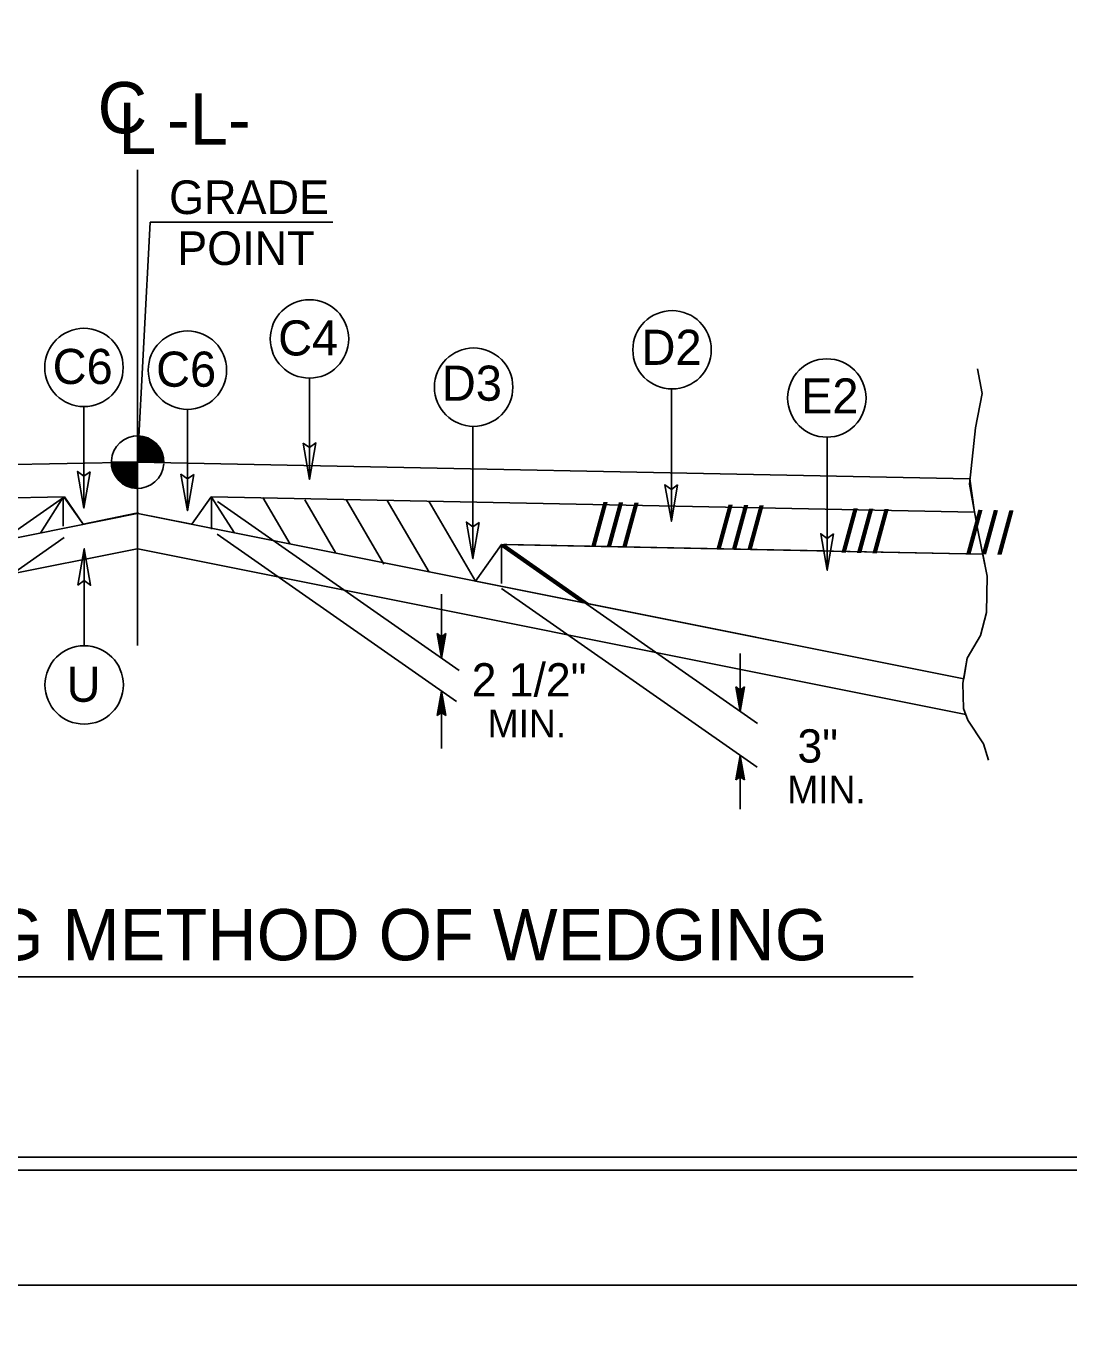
# Model space of a CAD drawing. Extents: x 1901718 to 1902220, y 193828 to 194187.
# Drawn here: x 1902003.79 to 1902024.12, y 194046.89 to 194072.58 of the extents above; entities that cross this region are included whole.
import ezdxf

# ---------------------------------------------------------------- set-up
doc = ezdxf.new("R2010")
doc.units = 0
for name, color, linetype in [('Old_Level_1', 7, 'Continuous'), ('Old_Level_11', 7, 'Continuous'), ('Old_Level_2', 7, 'Continuous'), ('Old_Level_20', 7, 'Continuous'), ('Old_Level_21', 7, 'Continuous'), ('Old_Level_3', 7, 'Continuous'), ('Sheet Border Standard 30in CELL', 7, 'Continuous'), ('Sheet Cutting Line CELL', 7, 'Continuous'), ('Sheet Plot Border Inside CELL', 7, 'Continuous'), ('Sheet Plot Border Outside CELL', 7, 'Continuous')]:
    doc.layers.add(name, color=color, linetype=linetype)

msp = doc.modelspace()

# ---------------------------------------------------------------- linework, layer by layer
at = {"layer": 'Old_Level_1'}
for p, q in [((1902005.956, 194064.077), (1902005.956, 194064.588)), ((1902005.445, 194064.077), (1902005.956, 194064.077)), ((1902005.953, 194063.566), (1902005.953, 194064.071)), ((1902005.956, 194064.077), (1902005.956, 194063.566)), ((1902006.468, 194064.077), (1902005.956, 194064.077)), ((1902005.956, 194063.566), (1902005.956, 194064.077)), ((1902004.51, 194063.386), (1901999.935, 194060.183)), ((1902008.4, 194063.386), (1902008.93, 194062.478)), ((1902007.513, 194063.312), (1902012.226, 194060.011)), ((1902009.215, 194063.344), (1902009.823, 194062.303)), ((1902010.023, 194063.346), (1902010.757, 194062.089)), ((1902010.825, 194063.33), (1902011.642, 194061.928)), ((1902011.636, 194063.313), (1902012.545, 194061.755)), ((1902004.521, 194062.604), (1902000.044, 194059.469)), ((1902007.507, 194062.67), (1902012.174, 194059.403)), ((1902005.947, 194062.385), (1901989.833, 194059.162)), ((1902005.959, 194062.385), (1902022.11, 194059.154)), ((1902012.546, 194061.755), (1902013.055, 194062.471)), ((1902013.055, 194062.471), (1902022.44, 194062.283)), ((1902013.055, 194062.471), (1902013.055, 194061.71)), ((1902013.056, 194062.471), (1902018.046, 194058.976)), ((1902012.545, 194061.755), (1902014.69, 194061.326)), ((1902013.055, 194061.611), (1902018.037, 194058.121)), ((1902011.882, 194061.501), (1902011.882, 194060.253)), ((1902011.882, 194060.253), (1902011.798, 194060.731)), ((1902011.882, 194060.668), (1902011.798, 194060.731)), ((1902011.882, 194060.253), (1902011.809, 194060.722)), ((1902011.821, 194060.713), (1902011.882, 194060.253)), ((1902011.882, 194060.253), (1902011.834, 194060.704)), ((1902011.846, 194060.695), (1902011.882, 194060.253)), ((1902011.882, 194060.253), (1902011.857, 194060.686)), ((1902011.869, 194060.678), (1902011.882, 194060.253)), ((1902011.882, 194060.253), (1902011.966, 194060.731)), ((1902011.966, 194060.731), (1902011.882, 194060.668)), ((1902011.954, 194060.722), (1902011.882, 194060.253)), ((1902011.882, 194060.253), (1902011.942, 194060.713)), ((1902011.93, 194060.704), (1902011.882, 194060.253)), ((1902011.882, 194060.253), (1902011.918, 194060.695)), ((1902011.906, 194060.686), (1902011.882, 194060.253)), ((1902011.882, 194060.253), (1902011.894, 194060.678)), ((1902011.882, 194060.668), (1902011.882, 194060.253)), ((1902017.708, 194060.342), (1902017.708, 194059.213)), ((1902011.882, 194059.607), (1902011.798, 194059.13)), ((1902011.809, 194059.139), (1902011.882, 194059.607)), ((1902011.882, 194059.607), (1902011.821, 194059.148)), ((1902011.834, 194059.157), (1902011.882, 194059.607)), ((1902011.882, 194059.607), (1902011.846, 194059.166)), ((1902011.857, 194059.174), (1902011.882, 194059.607)), ((1902011.882, 194059.607), (1902011.869, 194059.183)), ((1902011.882, 194059.607), (1902011.882, 194058.491)), ((1902011.882, 194059.607), (1902011.966, 194059.13)), ((1902011.882, 194059.192), (1902011.882, 194059.607)), ((1902011.894, 194059.183), (1902011.882, 194059.607)), ((1902011.882, 194059.607), (1902011.906, 194059.174)), ((1902011.918, 194059.166), (1902011.882, 194059.607)), ((1902011.882, 194059.607), (1902011.93, 194059.157)), ((1902011.942, 194059.148), (1902011.882, 194059.607)), ((1902011.882, 194059.607), (1902011.954, 194059.139)), ((1902017.708, 194059.213), (1902017.624, 194059.69)), ((1902017.708, 194059.629), (1902017.624, 194059.69)), ((1902017.708, 194059.213), (1902017.636, 194059.681)), ((1902017.648, 194059.673), (1902017.708, 194059.213)), ((1902017.708, 194059.213), (1902017.659, 194059.665)), ((1902017.671, 194059.655), (1902017.708, 194059.213)), ((1902017.708, 194059.213), (1902017.684, 194059.647)), ((1902017.695, 194059.637), (1902017.708, 194059.213)), ((1902017.708, 194059.213), (1902017.792, 194059.69)), ((1902017.792, 194059.69), (1902017.708, 194059.629)), ((1902017.78, 194059.681), (1902017.708, 194059.213)), ((1902017.708, 194059.213), (1902017.768, 194059.673)), ((1902017.756, 194059.665), (1902017.708, 194059.213)), ((1902017.708, 194059.213), (1902017.743, 194059.655)), ((1902017.732, 194059.647), (1902017.708, 194059.213)), ((1902017.708, 194059.213), (1902017.72, 194059.637)), ((1902017.708, 194059.629), (1902017.708, 194059.213)), ((1902011.798, 194059.13), (1902011.882, 194059.192)), ((1902011.882, 194059.192), (1902011.966, 194059.13)), ((1902017.708, 194058.352), (1902017.624, 194057.875)), ((1902017.636, 194057.884), (1902017.708, 194058.352)), ((1902017.708, 194058.352), (1902017.648, 194057.893)), ((1902017.659, 194057.902), (1902017.708, 194058.352)), ((1902017.708, 194058.352), (1902017.671, 194057.911)), ((1902017.684, 194057.92), (1902017.708, 194058.352)), ((1902017.708, 194058.352), (1902017.695, 194057.928)), ((1902017.708, 194058.352), (1902017.708, 194057.305)), ((1902017.708, 194058.352), (1902017.792, 194057.875)), ((1902017.708, 194057.938), (1902017.708, 194058.352)), ((1902017.72, 194057.928), (1902017.708, 194058.352)), ((1902017.708, 194058.352), (1902017.732, 194057.92)), ((1902017.743, 194057.911), (1902017.708, 194058.352)), ((1902017.708, 194058.352), (1902017.756, 194057.902)), ((1902017.768, 194057.893), (1902017.708, 194058.352)), ((1902017.708, 194058.352), (1902017.78, 194057.884)), ((1902017.624, 194057.875), (1902017.708, 194057.938)), ((1902017.708, 194057.938), (1902017.792, 194057.875))]:
    msp.add_line(p, q, dxfattribs=at)
for points in [[(1902022.34, 194065.896), (1902022.426, 194065.42), (1902022.297, 194064.744), (1902022.181, 194063.649), (1902022.34, 194062.785), (1902022.527, 194061.849), (1902022.513, 194061.143), (1902022.397, 194060.697), (1902022.138, 194060.25), (1902022.052, 194059.761), (1902022.066, 194059.271), (1902022.152, 194059.04), (1902022.454, 194058.579), (1902022.555, 194058.262)], [(1902005.961, 194064.588), (1902005.961, 194064.588), (1902005.961, 194064.077)], [(1902005.971, 194064.588), (1902005.971, 194064.077)], [(1902005.982, 194064.588), (1902005.982, 194064.077)], [(1902005.992, 194064.587), (1902005.992, 194064.077)], [(1902006.003, 194064.587), (1902006.003, 194064.077)], [(1902006.012, 194064.585), (1902006.012, 194064.077)], [(1902006.023, 194064.585), (1902006.023, 194064.077)], [(1902006.032, 194064.583), (1902006.032, 194064.077)], [(1902006.043, 194064.581), (1902006.043, 194064.077)], [(1902006.053, 194064.579), (1902006.053, 194064.077)], [(1902006.064, 194064.578), (1902006.064, 194064.077)], [(1902006.074, 194064.575), (1902006.074, 194064.077)], [(1902006.084, 194064.572), (1902006.084, 194064.077)], [(1902006.094, 194064.569), (1902006.094, 194064.077)], [(1902006.104, 194064.566), (1902006.104, 194064.077)], [(1902006.114, 194064.563), (1902006.114, 194064.077)], [(1902006.125, 194064.56), (1902006.125, 194064.077)], [(1902006.135, 194064.556), (1902006.135, 194064.077)], [(1902006.146, 194064.552), (1902006.146, 194064.077)], [(1902006.156, 194064.548), (1902006.155, 194064.077)], [(1902006.166, 194064.543), (1902006.166, 194064.077)], [(1902006.176, 194064.539), (1902006.176, 194064.077)], [(1902006.186, 194064.534), (1902006.186, 194064.077)], [(1902006.197, 194064.528), (1902006.197, 194064.077)], [(1902006.207, 194064.522), (1902006.207, 194064.077)], [(1902006.217, 194064.516), (1902006.217, 194064.077)], [(1902006.228, 194064.51), (1902006.227, 194064.077)], [(1902006.238, 194064.505), (1902006.238, 194064.077)], [(1902006.247, 194064.497), (1902006.247, 194064.077)], [(1902006.257, 194064.49), (1902006.257, 194064.077)], [(1902006.268, 194064.482), (1902006.268, 194064.077)], [(1902006.278, 194064.474), (1902006.278, 194064.077)], [(1902006.289, 194064.466), (1902006.289, 194064.077)], [(1902006.299, 194064.457), (1902006.299, 194064.077)], [(1902006.31, 194064.447), (1902006.31, 194064.077)], [(1902006.319, 194064.438), (1902006.319, 194064.077)], [(1902006.329, 194064.427), (1902006.329, 194064.077)], [(1902006.34, 194064.415), (1902006.34, 194064.077)], [(1902006.35, 194064.403), (1902006.35, 194064.077)], [(1902006.361, 194064.39), (1902006.361, 194064.077)], [(1902006.371, 194064.377), (1902006.37, 194064.077)], [(1902006.381, 194064.363), (1902006.381, 194064.077)], [(1902006.39, 194064.346), (1902006.39, 194064.077)], [(1902006.401, 194064.329), (1902006.401, 194064.077)], [(1902006.411, 194064.311), (1902006.411, 194064.077)], [(1902006.422, 194064.289), (1902006.422, 194064.077)], [(1902006.432, 194064.265), (1902006.432, 194064.077)], [(1902006.442, 194064.236), (1902006.442, 194064.077)], [(1902006.453, 194064.202), (1902006.453, 194064.077)], [(1902006.462, 194064.149), (1902006.462, 194064.077)], [(1902005.447, 194064.077), (1902005.447, 194064.021)], [(1902005.458, 194064.077), (1902005.458, 194063.961)], [(1902005.469, 194064.077), (1902005.469, 194063.924)], [(1902005.479, 194064.077), (1902005.479, 194063.895)], [(1902005.488, 194064.077), (1902005.488, 194063.869)], [(1902005.498, 194064.077), (1902005.498, 194063.848)], [(1902005.508, 194064.077), (1902005.508, 194063.829)], [(1902005.519, 194064.077), (1902005.519, 194063.811)], [(1902005.529, 194064.077), (1902005.529, 194063.795)], [(1902005.54, 194064.077), (1902005.54, 194063.779)], [(1902005.55, 194064.077), (1902005.55, 194063.766)], [(1902005.56, 194064.077), (1902005.56, 194063.753)], [(1902005.57, 194064.077), (1902005.57, 194063.741)], [(1902005.58, 194064.077), (1902005.58, 194063.729)], [(1902005.591, 194064.077), (1902005.591, 194063.719)], [(1902005.601, 194064.077), (1902005.601, 194063.71)], [(1902005.612, 194064.077), (1902005.612, 194063.699)], [(1902005.622, 194064.077), (1902005.621, 194063.69)], [(1902005.631, 194064.077), (1902005.631, 194063.681)], [(1902005.642, 194064.077), (1902005.642, 194063.674)], [(1902005.652, 194064.077), (1902005.652, 194063.666)], [(1902005.663, 194064.077), (1902005.663, 194063.659)], [(1902005.673, 194064.077), (1902005.673, 194063.651)], [(1902005.683, 194064.077), (1902005.683, 194063.644)], [(1902005.693, 194064.077), (1902005.693, 194063.638)], [(1902005.703, 194064.077), (1902005.703, 194063.632)], [(1902005.713, 194064.077), (1902005.713, 194063.627)], [(1902005.723, 194064.077), (1902005.723, 194063.621)], [(1902005.734, 194064.077), (1902005.734, 194063.616)], [(1902005.744, 194064.077), (1902005.744, 194063.611)], [(1902005.755, 194064.077), (1902005.755, 194063.606)], [(1902005.765, 194064.077), (1902005.765, 194063.603)], [(1902005.775, 194064.077), (1902005.775, 194063.599)], [(1902005.786, 194064.077), (1902005.786, 194063.594)], [(1902005.795, 194064.077), (1902005.795, 194063.591)], [(1902005.806, 194064.077), (1902005.806, 194063.588)], [(1902005.816, 194064.077), (1902005.816, 194063.585)], [(1902005.826, 194064.077), (1902005.826, 194063.583)], [(1902005.837, 194064.077), (1902005.836, 194063.579)], [(1902005.846, 194064.077), (1902005.846, 194063.578)], [(1902005.857, 194064.077), (1902005.857, 194063.575)], [(1902005.866, 194064.077), (1902005.866, 194063.573)], [(1902005.877, 194064.077), (1902005.877, 194063.572)], [(1902005.887, 194064.077), (1902005.887, 194063.57)], [(1902005.898, 194064.077), (1902005.898, 194063.569)], [(1902005.908, 194064.077), (1902005.908, 194063.567)], [(1902005.918, 194064.077), (1902005.918, 194063.567)], [(1902005.929, 194064.077), (1902005.928, 194063.566)], [(1902005.938, 194064.077), (1902005.938, 194063.566)], [(1902005.949, 194064.077), (1902005.949, 194063.566), (1902005.949, 194063.566)]]:
    msp.add_lwpolyline(points, dxfattribs=at)
for start, end in [(358.0003, 356.1713), (359.9905, 89.9905), (179.9905, 268.7186), (269.6533, 269.9905)]:
    msp.add_arc((1902005.956, 194064.077), 0.512, start, end, dxfattribs=at)
at = {"layer": 'Old_Level_11'}
for p, q in [((1902005.952, 194060.497), (1902005.952, 194069.78)), ((1902009.308, 194065.717), (1902009.308, 194063.739)), ((1902016.366, 194065.504), (1902016.366, 194062.923)), ((1902004.91, 194065.16), (1902004.91, 194063.182)), ((1902006.927, 194065.107), (1902006.927, 194063.129)), ((1902012.495, 194064.775), (1902012.495, 194062.194)), ((1902019.407, 194064.563), (1902019.407, 194061.968)), ((1902005.952, 194064.077), (1901989.717, 194063.753)), ((1902005.952, 194064.077), (1902022.189, 194063.753)), ((1902005.954, 194064.077), (1902022.189, 194063.753)), ((1902022.189, 194063.753), (1902022.282, 194063.101)), ((1902004.528, 194063.399), (1901989.624, 194063.101)), ((1902004.067, 194062.704), (1902004.507, 194063.393)), ((1902004.507, 194063.393), (1902004.507, 194062.827)), ((1902004.893, 194062.864), (1902004.528, 194063.399)), ((1902004.528, 194063.381), (1902004.893, 194062.864)), ((1902007.389, 194063.399), (1902007.013, 194062.864)), ((1902007.389, 194063.399), (1902022.282, 194063.101)), ((1902007.839, 194062.704), (1902007.399, 194063.393)), ((1902007.399, 194063.393), (1902007.399, 194062.769)), ((1902005.977, 194063.079), (1901989.839, 194059.851)), ((1902005.929, 194063.079), (1902004.893, 194062.864)), ((1902005.929, 194063.079), (1902022.068, 194059.851)), ((1902007.013, 194062.864), (1902005.929, 194063.079)), ((1902004.914, 194060.494), (1902004.914, 194062.388)), ((1902013.157, 194062.47), (1902013.101, 194062.47)), ((1902013.101, 194062.47), (1902014.751, 194061.315)), ((1902019.34, 194062.345), (1902013.157, 194062.47)), ((1902022.44, 194062.283), (1902019.471, 194062.342)), ((1902014.751, 194061.315), (1902014.751, 194061.315)), ((1902014.751, 194061.315), (1902014.751, 194061.315)), ((1902014.751, 194061.315), (1902014.751, 194061.315)), ((1902014.751, 194061.315), (1902014.751, 194061.315)), ((1902014.751, 194061.315), (1902014.751, 194061.315)), ((1902014.751, 194061.315), (1902014.751, 194061.315)), ((1902014.751, 194061.315), (1902022.068, 194059.851)), ((1902022.068, 194059.851), (1902022.138, 194060.25)), ((1902022.068, 194059.851), (1902022.068, 194059.851)), ((1901991.79, 194054.031), (1902021.085, 194054.031))]:
    msp.add_line(p, q, dxfattribs=at)
for points in [[(1902009.186, 194064.447), (1902009.308, 194063.739), (1902009.434, 194064.451), (1902009.308, 194064.361)], [(1902005.032, 194063.891), (1902004.91, 194063.182), (1902004.784, 194063.895), (1902004.91, 194063.804)], [(1902007.05, 194063.837), (1902006.927, 194063.129), (1902006.801, 194063.841), (1902006.927, 194063.751)], [(1902016.488, 194063.632), (1902016.366, 194062.923), (1902016.24, 194063.636), (1902016.366, 194063.545)], [(1902012.618, 194062.902), (1902012.495, 194062.194), (1902012.369, 194062.906), (1902012.495, 194062.816)], [(1902019.529, 194062.676), (1902019.407, 194061.968), (1902019.281, 194062.68), (1902019.407, 194062.59)], [(1902004.792, 194061.679), (1902004.914, 194062.388), (1902005.04, 194061.675), (1902004.914, 194061.766)], [(1902013.041, 194062.451), (1902012.546, 194061.755), (1902014.628, 194061.339)]]:
    msp.add_lwpolyline(points, close=True, dxfattribs=at)
for points in [[(1902019.471, 194062.342), (1902019.407, 194061.968), (1902019.34, 194062.345)], [(1902022.138, 194060.25), (1902022.397, 194060.697), (1902022.513, 194061.143), (1902022.527, 194061.849), (1902022.44, 194062.283)]]:
    msp.add_lwpolyline(points, dxfattribs=at)
for centre in [(1902009.308, 194066.482), (1902016.38, 194066.27), (1902004.91, 194065.925), (1902006.928, 194065.872), (1902012.51, 194065.54), (1902019.399, 194065.329), (1902004.914, 194059.729)]:
    msp.add_circle(centre, 0.765, dxfattribs=at)
at = {"layer": 'Old_Level_3'}
for q in [(1902005.954, 194064.077), (1902009.761, 194068.761)]:
    msp.add_line((1902006.204, 194068.761), q, dxfattribs=at)
at = {"layer": 'Sheet Border Standard 30in CELL'}
msp.add_lwpolyline([(1902132.544, 194155.514), (1901982.544, 194155.514), (1901982.544, 194050.514), (1902132.544, 194050.514)], close=True, dxfattribs=at)
at = {"layer": 'Sheet Cutting Line CELL'}
for p, q in [((1901965.844, 194048.014), (1902134.244, 194048.014)), ((1902134.244, 194048.014), (1901965.844, 194048.014))]:
    msp.add_line(p, q, dxfattribs=at)
at = {"layer": 'Sheet Plot Border Inside CELL'}
msp.add_lwpolyline([(1902133.794, 194155.769), (1901967.144, 194155.769), (1901967.144, 194050.259), (1902133.794, 194050.259)], close=True, dxfattribs=at)
at = {"layer": 'Sheet Plot Border Outside CELL'}
for points in [[(1902134.244, 194158.014), (1901965.844, 194158.014), (1901965.844, 194048.014), (1902134.244, 194048.014)], [(1902134.244, 194048.014), (1901965.844, 194048.014), (1901965.844, 193938.014), (1902134.244, 193938.014)]]:
    msp.add_lwpolyline(points, close=True, dxfattribs=at)

# ---------------------------------------------------------------- texts
at = {"layer": 'Old_Level_1'}
for height, rotation, p in [(0.8139, 358.8553, (1902014.804, 194062.445)), (0.8139, 358.8536, (1902017.245, 194062.395)), (0.8142, 358.8554, (1902019.683, 194062.323)), (0.8142, 358.8537, (1902022.117, 194062.294))]:
    msp.add_text('/// ', height=height, rotation=rotation, dxfattribs=at).set_placement(p)
at = {"layer": 'Old_Level_11'}
for s, p in [('GRADE', (1902006.57, 194068.919)), ('POINT', (1902006.728, 194067.925))]:
    msp.add_text(s, height=0.656, dxfattribs=at).set_placement(p)
at = {"layer": 'Old_Level_2'}
msp.add_text('C', height=1, dxfattribs=at).set_placement((1902005.176, 194070.496))
for s, p in [('L', (1902005.578, 194070.092)), ('-L-', (1902006.527, 194070.275))]:
    msp.add_text(s, height=1, rotation=359.9469, dxfattribs=at).set_placement(p)
at = {"layer": 'Old_Level_20'}
for s, height, p in [('C4', 0.6851, (1902008.697, 194066.159)), ('D2', 0.6851, (1902015.785, 194065.976)), ('C6', 0.6851, (1902004.299, 194065.602)), ('C6', 0.6851, (1902006.317, 194065.549)), ('D3', 0.6851, (1902011.891, 194065.276)), ('E2', 0.6851, (1902018.896, 194065.027)), ('U', 0.685, (1902004.571, 194059.4)), ('2 1/2"', 0.6491, (1902012.472, 194059.504)), ('3"', 0.6491, (1902018.826, 194058.214))]:
    msp.add_text(s, height=height, dxfattribs=at).set_placement(p)
at = {"layer": 'Old_Level_21'}
for s, height, p in [('MIN.', 0.5424, (1902012.784, 194058.705)), ('MIN.', 0.5424, (1902018.627, 194057.416)), ('DETAIL SHOWING METHOD OF WEDGING', 1, (1901992.529, 194054.355))]:
    msp.add_text(s, height=height, dxfattribs=at).set_placement(p)

doc.saveas('drawing.dxf')
